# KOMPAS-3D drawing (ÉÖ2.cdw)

Referenced files in F:\1я детская\: РЩ2.cdw
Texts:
  Электроснабжение первой детской клинической больницы  по адресу: г. Иваново, ул. Мальцева д.3
  Microsoft
  Текст на чертеже
  Размерные надписи
  Шероховатость
  Линия-выноска #1
  Линия-выноска #2
  Линия-выноска #3
  Отклонения формы и база
  Заголовок таблицы
  Ячейка таблицы
  Стрелка вида
  Обозначение изменения
  Фигурная скобка
  Номер узла
  Марка координационной оси
  VRCB
  Выносная надпись
  Обозначение узла
  Марка/позиционное обозначение с линией-выноской
  Марка/позиционное обозначение на линии
  Марка/позиционное обозначение без линии-выноски
  ВА 47-29 (1)
  ВА 47-29 (3)
  Номер группы
  Р кВт
  Ток, А
  Гр1
  Гр2
  Гр3
  Гр4
  Освещение
  ВВГ 5х10 мм 2  скрыто в ст.
  гофр. трубе от ВРУ
  ВВГнгLS 3х1,5 cкрыто
  РЩ-2 (ЩРВ-24)
  Гр5
  Гр6
  Бактарецидные
  лампы
  Гр7
  Розетки
  Гр8
  Гр9
  АД12М
  CONTINUOUS0
  Электроснабжение первой детской клинической больницы
  по адресу: г. Иваново, ул. Мальцева д.3
  ГИП
  Разработ
  Однолинейная расчётная схема щита
  РЩ-2
  Кочетков
  ООО "Мастер Лайт"
Dimensions and other numbers on the sheet: 2012-0011-ЭС; 7; 10А; 16А; 0.5; 0.12; 0.24; 1.1; 1.0; 5.05; 16А Iсраб=30мА; 4; 1:1; 5; 0; 1; 2; 3; 6; 8; 9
